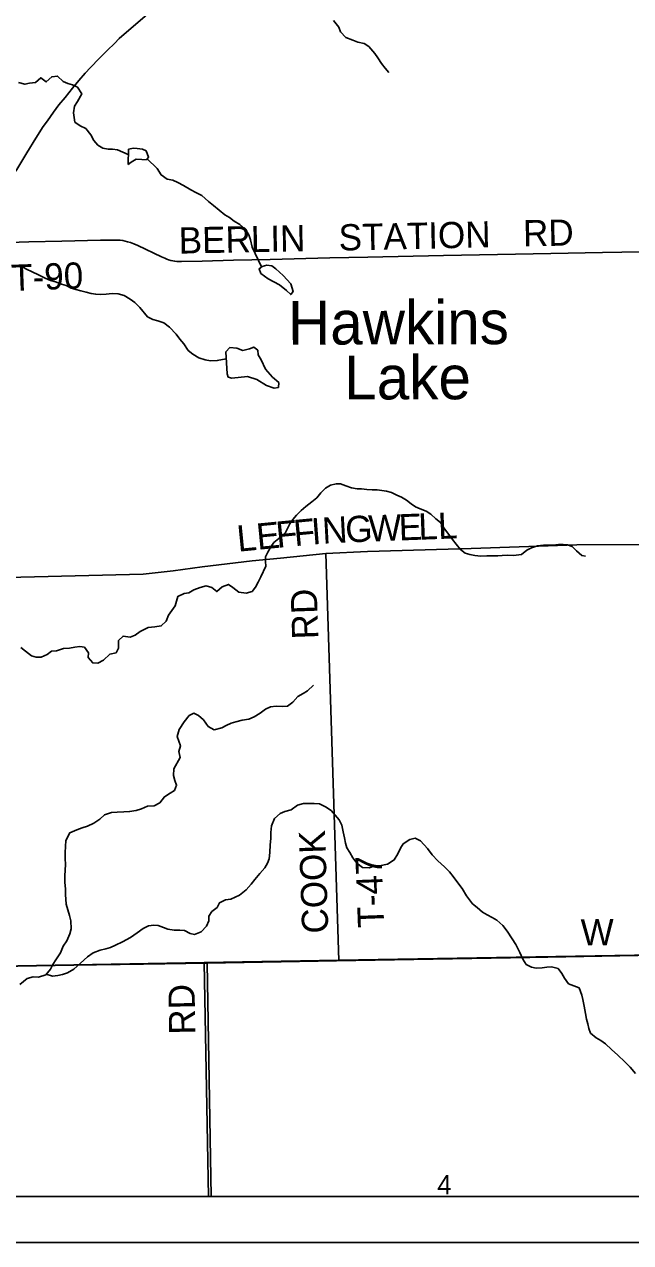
# Model space of a CAD drawing. Extents: x 0 to 34, y 0 to 22.
# Drawn here: x 5.185 to 6.498, y 13.024 to 15.664 of the extents above; entities that cross this region are included whole.
import ezdxf

# ---------------------------------------------------------------- set-up
doc = ezdxf.new("R2010")
doc.units = 0
for name, color, linetype in [('GM_X_Corporation', 7, 'Continuous'), ('GM_X_County_Road', 7, 'Continuous'), ('GM_X_County_Road_Text', 7, 'Continuous'), ('GM_X_Minor_Lake', 7, 'Continuous'), ('GM_X_Minor_River', 7, 'Continuous'), ('GM_X_Minor_River_Text', 7, 'Continuous'), ('GM_X_Rail_Line', 7, 'Continuous'), ('GM_X_Section_Text', 7, 'Continuous'), ('GM_X_Township_Road', 7, 'Continuous'), ('GM_X_Township_Road_Text', 7, 'Continuous'), ('SH_Data', 7, 'Continuous')]:
    doc.layers.add(name, color=color, linetype=linetype)

msp = doc.modelspace()

# ---------------------------------------------------------------- linework, layer by layer
at = {"layer": 'GM_X_Corporation'}
msp.add_lwpolyline([(7.0169, 18.7868), (5.8701, 18.7643), (5.4919, 18.7569), (4.784, 18.7437), (3.4438, 18.7173), (3.4438, 13.5923), (3.5133, 13.5939), (4.9278, 13.619), (5.5741, 13.6306), (5.8662, 13.6357), (7.1049, 13.6572)], dxfattribs=at)
for points in [[(3.5203, 13.1239), (9.7254, 13.1239), (9.7218, 13.5975), (9.7208, 13.7198), (9.6344, 13.7177), (8.628, 13.6922), (8.1719, 13.6806), (7.1291, 13.6578), (7.1049, 13.6572), (5.8662, 13.6357), (5.5741, 13.6306), (4.9278, 13.619), (3.5133, 13.5939)], [(4.5581, 13.1239), (5.5897, 13.1239), (5.5806, 13.6297), (5.4429, 13.6273), (5.0357, 13.6214), (4.6031, 13.6154), (4.55, 13.6145)], [(5.5897, 13.1239), (6.6031, 13.1239), (6.5922, 13.6472), (6.2801, 13.6415), (5.861, 13.6345), (5.5806, 13.6297)]]:
    msp.add_lwpolyline(points, close=True, dxfattribs=at)
at = {"layer": 'GM_X_County_Road'}
msp.add_lwpolyline([(3.5135, 13.5934), (4.928, 13.6184), (5.5743, 13.6301), (5.8664, 13.6351), (7.1051, 13.6567)], dxfattribs=at)
at = {"layer": 'GM_X_Minor_Lake'}
for points in [[(5.4097, 15.3599), (5.416, 15.3654), (5.4269, 15.3714), (5.4391, 15.3713), (5.449, 15.3704), (5.4538, 15.3762), (5.4485, 15.3897), (5.4408, 15.3937), (5.429, 15.3946), (5.421, 15.3952), (5.41, 15.3934)], [(5.41, 15.3934), (5.4097, 15.3599)], [(5.6997, 15.1394), (5.6934, 15.1343), (5.6967, 15.1242), (5.7129, 15.1124), (5.7372, 15.0993), (5.7523, 15.0871), (5.7617, 15.0782), (5.7668, 15.0851), (5.7619, 15.1014), (5.7455, 15.1196), (5.7295, 15.1337), (5.7206, 15.1407), (5.71, 15.142)], [(5.71, 15.142), (5.6997, 15.1394)], [(5.6238, 14.9065), (5.6266, 14.8993), (5.6339, 14.8969), (5.6684, 14.9007), (5.6883, 14.8943), (5.7096, 14.8815), (5.7261, 14.8758), (5.7352, 14.8772), (5.7361, 14.8875), (5.7221, 14.8993), (5.7072, 14.9168), (5.6976, 14.9368), (5.6913, 14.9476), (5.6903, 14.9575), (5.6818, 14.9645), (5.6727, 14.9605), (5.658, 14.9571), (5.6449, 14.9621), (5.6297, 14.9633), (5.6211, 14.954)], [(5.6211, 14.954), (5.6238, 14.9065)]]:
    msp.add_lwpolyline(points, dxfattribs=at)
at = {"layer": 'GM_X_Minor_River'}
for points in [[(5.8547, 15.6719), (5.8657, 15.6577), (5.8697, 15.6479), (5.881, 15.6353), (5.8964, 15.6296), (5.9075, 15.6253), (5.9213, 15.6222), (5.931, 15.6155), (5.9438, 15.601), (5.9505, 15.5913), (5.9588, 15.5793), (5.9663, 15.5692), (5.9745, 15.5592)], [(5.172, 15.5376), (5.1857, 15.5341), (5.1956, 15.5362), (5.2089, 15.5377), (5.22, 15.5482), (5.232, 15.539), (5.2439, 15.5503), (5.2565, 15.5517), (5.2689, 15.5399), (5.2785, 15.5359), (5.2889, 15.5327), (5.2996, 15.5276), (5.3091, 15.513), (5.3, 15.4969), (5.2934, 15.4864), (5.291, 15.4723), (5.2924, 15.4621), (5.2942, 15.4519), (5.3058, 15.4438)], [(5.3058, 15.4438), (5.3177, 15.438), (5.3283, 15.4242), (5.335, 15.4118), (5.344, 15.4017), (5.3548, 15.3955), (5.3659, 15.3935), (5.3754, 15.3933), (5.3861, 15.3921), (5.4099, 15.3815)], [(5.4505, 15.3721), (5.4723, 15.3511), (5.4809, 15.3377), (5.4937, 15.3285), (5.5063, 15.3261), (5.5171, 15.3214), (5.5294, 15.3149), (5.5452, 15.3053), (5.5564, 15.2991), (5.5691, 15.2926), (5.5835, 15.28), (5.5943, 15.2715), (5.6068, 15.2608), (5.6192, 15.2512), (5.6288, 15.245), (5.6396, 15.2376), (5.6512, 15.2299), (5.6636, 15.2196), (5.6711, 15.208), (5.6744, 15.197), (5.6782, 15.1807), (5.6988, 15.1387)], [(5.1747, 15.1411), (5.189, 15.1331), (5.2017, 15.1273), (5.2155, 15.1208), (5.2294, 15.1135), (5.2413, 15.1088), (5.2524, 15.1057), (5.2651, 15.101), (5.2754, 15.0978), (5.2858, 15.0924), (5.2961, 15.0896), (5.3069, 15.0864), (5.3187, 15.0833), (5.3291, 15.0809), (5.3394, 15.0788), (5.3504, 15.0787), (5.3622, 15.0794), (5.3747, 15.0804), (5.3877, 15.0796), (5.4011, 15.0765), (5.4142, 15.0681), (5.4243, 15.0611), (5.4348, 15.0503), (5.4512, 15.0302), (5.4628, 15.0243), (5.4735, 15.0212), (5.4865, 15.0169), (5.4993, 15.0077), (5.5133, 14.9928), (5.5216, 14.9813), (5.5302, 14.9712), (5.5393, 14.9573), (5.5497, 14.9488), (5.5629, 14.9412), (5.5767, 14.9366), (5.5881, 14.9345), (5.6026, 14.9353), (5.622, 14.9393)], [(5.6969, 14.4663), (5.7078, 14.4899), (5.7068, 14.4996), (5.7068, 14.5102), (5.712, 14.5198), (5.7184, 14.5313), (5.7251, 14.5408), (5.7399, 14.5523), (5.7497, 14.5612), (5.7545, 14.5711), (5.7601, 14.5814), (5.7665, 14.591), (5.774, 14.6005), (5.7842, 14.6101), (5.7948, 14.6189), (5.8073, 14.6289), (5.8182, 14.6381), (5.8272, 14.6489), (5.837, 14.6588), (5.848, 14.665), (5.8602, 14.6681), (5.8697, 14.6678), (5.8815, 14.6641), (5.8937, 14.6593), (5.9059, 14.6571), (5.9154, 14.6576), (5.9265, 14.6558), (5.9386, 14.6551), (5.9493, 14.6552), (5.9691, 14.6523), (5.9805, 14.6494), (5.9916, 14.6434), (6.0015, 14.6389), (6.013, 14.6325), (6.0226, 14.6246), (6.0325, 14.6186), (6.0425, 14.6141), (6.0554, 14.6086), (6.0654, 14.6022), (6.0761, 14.592), (6.0861, 14.5845), (6.0953, 14.5709), (6.1042, 14.5584), (6.1127, 14.5474), (6.12, 14.5376), (6.1296, 14.5255), (6.1399, 14.518), (6.1502, 14.5151), (6.1609, 14.5129), (6.1738, 14.5111), (6.1864, 14.5119), (6.1978, 14.5124), (6.2107, 14.5121), (6.2202, 14.513), (6.232, 14.5138), (6.2442, 14.5132), (6.2617, 14.5148), (6.2737, 14.5244), (6.2836, 14.5298), (6.2965, 14.5341), (6.3094, 14.535), (6.3307, 14.5352), (6.3421, 14.5364), (6.3524, 14.5369), (6.3619, 14.5358), (6.3714, 14.5321), (6.3814, 14.5226), (6.3925, 14.5129), (6.4005, 14.5114)], [(5.1868, 14.3057), (5.2003, 14.2957), (5.2102, 14.2924), (5.2208, 14.2926), (5.2339, 14.2986), (5.2436, 14.3056), (5.2542, 14.3066), (5.2693, 14.311), (5.2826, 14.3121), (5.2943, 14.3142), (5.3045, 14.3155), (5.3147, 14.3142), (5.3237, 14.3018), (5.3231, 14.2919), (5.3328, 14.28), (5.3438, 14.2794), (5.3558, 14.2861), (5.37, 14.2989), (5.3835, 14.3018), (5.3887, 14.3118), (5.3884, 14.3285), (5.3984, 14.3382), (5.4136, 14.3359), (5.4249, 14.3399), (5.4357, 14.3481), (5.453, 14.3571), (5.467, 14.3585), (5.4814, 14.3603), (5.4922, 14.3708), (5.4972, 14.3834), (5.5042, 14.3934), (5.5116, 14.4038), (5.5141, 14.4142), (5.5169, 14.4237), (5.5308, 14.4304), (5.541, 14.4321), (5.5519, 14.4381), (5.5655, 14.4436), (5.5787, 14.4473), (5.5909, 14.4434), (5.6016, 14.4348), (5.6136, 14.4453), (5.6267, 14.4501), (5.6363, 14.4435), (5.649, 14.4335), (5.665, 14.4311), (5.6782, 14.4348), (5.6856, 14.4444), (5.6911, 14.4552), (5.6969, 14.4663)], [(5.1772, 14.3134), (5.1868, 14.3057)], [(5.3099, 13.9225), (5.3212, 13.9261), (5.3354, 13.9328), (5.3485, 13.9415), (5.3586, 13.9508), (5.3733, 13.956), (5.3854, 13.957), (5.3998, 13.9573), (5.4126, 13.9579), (5.427, 13.9604), (5.4387, 13.9641), (5.4518, 13.9697), (5.4662, 13.9703), (5.4779, 13.9766), (5.4882, 13.9901), (5.5002, 13.9976), (5.5099, 14.0038), (5.5143, 14.0149), (5.5107, 14.0255), (5.5078, 14.0361), (5.5087, 14.0509), (5.5219, 14.0751), (5.5194, 14.0883), (5.5229, 14.1002), (5.5193, 14.1104), (5.5154, 14.1205), (5.5204, 14.1358), (5.5307, 14.1524), (5.5418, 14.1659), (5.5519, 14.171), (5.5619, 14.1659), (5.5727, 14.157), (5.5828, 14.1424), (5.5958, 14.135), (5.6124, 14.1391), (5.6222, 14.1446), (5.6331, 14.1494), (5.6428, 14.1526), (5.6564, 14.1559), (5.6712, 14.1585), (5.6824, 14.1633), (5.6955, 14.1715), (5.7068, 14.1801), (5.7177, 14.1848), (5.7305, 14.1862), (5.743, 14.1857), (5.7551, 14.1863), (5.7667, 14.1953), (5.7771, 14.2076), (5.7887, 14.2136), (5.7985, 14.2198), (5.8115, 14.2322)], [(5.2319, 13.6054), (5.2457, 13.601), (5.2574, 13.6028), (5.2676, 13.6049), (5.2778, 13.6085), (5.292, 13.6164), (5.3066, 13.6295), (5.3211, 13.6435), (5.3334, 13.6517), (5.3489, 13.6577), (5.3609, 13.6606), (5.3715, 13.6635), (5.3824, 13.6682), (5.397, 13.6757), (5.4143, 13.6852), (5.4293, 13.6953), (5.442, 13.7047), (5.4536, 13.7106), (5.4653, 13.712), (5.4748, 13.711), (5.4859, 13.7067), (5.4958, 13.7031), (5.5095, 13.7011), (5.5216, 13.7009), (5.5319, 13.7), (5.5437, 13.6938), (5.5536, 13.6913), (5.5675, 13.6973), (5.579, 13.7096), (5.5841, 13.7215), (5.5847, 13.7314), (5.591, 13.7414), (5.6022, 13.7503), (5.6073, 13.7603), (5.6204, 13.767), (5.6321, 13.7684), (5.6506, 13.7767), (5.6651, 13.788), (5.6763, 13.8004), (5.6837, 13.8108), (5.6948, 13.8239), (5.7059, 13.8363), (5.7114, 13.8459), (5.715, 13.8558), (5.7163, 13.8695), (5.7171, 13.8859), (5.7188, 13.8996), (5.7189, 13.9129), (5.7202, 13.927), (5.7267, 13.9431), (5.7386, 13.9535), (5.7488, 13.9579), (5.7631, 13.962), (5.7765, 13.9721), (5.7894, 13.9754), (5.8026, 13.9753), (5.8125, 13.9755), (5.8242, 13.9746), (5.8372, 13.968), (5.8491, 13.9606), (5.8584, 13.9498), (5.8666, 13.94), (5.8724, 13.9288), (5.8757, 13.9144), (5.8783, 13.9008), (5.8808, 13.8894), (5.8836, 13.8792), (5.8902, 13.8695), (5.8965, 13.8578), (5.9047, 13.8462), (5.9173, 13.8369), (5.9318, 13.8357), (5.9438, 13.8401), (5.9544, 13.8407), (5.9718, 13.8437), (5.986, 13.8531), (5.9937, 13.8665), (5.9996, 13.8784), (6.0054, 13.888), (6.0197, 13.8974), (6.0317, 13.9003), (6.0432, 13.8948), (6.0579, 13.8776), (6.068, 13.8645), (6.0804, 13.8514), (6.0947, 13.838), (6.1058, 13.8272), (6.1136, 13.8171), (6.1221, 13.8063), (6.133, 13.7909), (6.1428, 13.7751), (6.156, 13.7583), (6.166, 13.7501), (6.1776, 13.7401), (6.1875, 13.7342), (6.1982, 13.7283), (6.2086, 13.7225), (6.2213, 13.7113), (6.231, 13.699), (6.2415, 13.6824), (6.2497, 13.6697)], [(5.1748, 13.5833), (5.1905, 13.5962), (5.2037, 13.5998), (5.215, 13.5989), (5.2309, 13.6042), (5.2409, 13.6161), (5.2464, 13.6265), (5.2526, 13.6369), (5.263, 13.6515), (5.2684, 13.666), (5.2769, 13.678), (5.2834, 13.6929), (5.2862, 13.704), (5.2855, 13.7211), (5.2827, 13.7324), (5.279, 13.7449), (5.2754, 13.757), (5.2744, 13.768), (5.2739, 13.7774), (5.2736, 13.7907), (5.2723, 13.8044), (5.2724, 13.8192), (5.2733, 13.8306), (5.2738, 13.8439), (5.2732, 13.8557), (5.2733, 13.869), (5.2735, 13.8826), (5.2744, 13.8952), (5.2828, 13.9121), (5.2986, 13.9185), (5.3099, 13.9225)], [(6.2497, 13.6697), (6.2584, 13.6524), (6.2651, 13.6381), (6.2721, 13.6268), (6.2836, 13.6209), (6.2939, 13.6185), (6.3063, 13.6191), (6.3165, 13.6208), (6.3268, 13.6218), (6.3412, 13.6179), (6.349, 13.6074), (6.3549, 13.5972), (6.3638, 13.5849), (6.3753, 13.5801), (6.3867, 13.5758), (6.3923, 13.5603), (6.3948, 13.5505), (6.3977, 13.5361), (6.4006, 13.5202), (6.4027, 13.5081), (6.4056, 13.4983), (6.408, 13.4881), (6.4116, 13.4779), (6.4236, 13.4675), (6.4339, 13.4616), (6.4439, 13.4546), (6.4566, 13.4427), (6.4705, 13.4304), (6.4859, 13.4159), (6.4971, 13.4039), (6.5087, 13.3901)]]:
    msp.add_lwpolyline(points, dxfattribs=at)
at = {"layer": 'GM_X_Rail_Line'}
msp.add_lwpolyline([(5.1658, 15.3457), (5.19, 15.3853), (5.2095, 15.4175), (5.2254, 15.4423), (5.2345, 15.455), (5.2477, 15.4735), (5.2594, 15.4891), (5.2727, 15.5054), (5.2886, 15.5253), (5.303, 15.5422), (5.3163, 15.5578), (5.3282, 15.5705), (5.3469, 15.5897), (5.3648, 15.608), (5.3797, 15.6226), (5.3904, 15.6328), (5.4967, 15.7256)], dxfattribs=at)
at = {"layer": 'GM_X_Township_Road'}
for p, q in [((5.8664, 13.6351), (5.8379, 14.517)), ((5.5838, 13.1239), (5.5743, 13.6301))]:
    msp.add_line(p, q, dxfattribs=at)
for points in [[(5.1306, 15.1906), (5.1942, 15.1923), (5.2656, 15.1942), (5.3496, 15.1961), (5.3786, 15.1965), (5.3869, 15.1963), (5.3925, 15.1959), (5.3977, 15.1953), (5.4027, 15.1943), (5.4084, 15.1928), (5.4147, 15.1909), (5.4216, 15.1881), (5.4302, 15.1844), (5.482, 15.1601), (5.4887, 15.1569), (5.4931, 15.1551), (5.4973, 15.1536), (5.502, 15.1523), (5.5064, 15.1512), (5.5106, 15.1504), (5.5147, 15.15), (5.5194, 15.1498), (5.5253, 15.1497), (5.5702, 15.1508), (5.6375, 15.1527), (5.7172, 15.1546), (5.8462, 15.1577), (5.9291, 15.1594), (6.093, 15.1628), (6.2492, 15.166), (6.3255, 15.1672), (6.4372, 15.1693), (6.6899, 15.1737)], [(7.1047, 14.5497), (6.8428, 14.5444), (6.5863, 14.5369), (6.3815, 14.5363), (6.1527, 14.5277), (5.9285, 14.5217), (5.8379, 14.517), (5.7397, 14.507), (5.678, 14.5012), (5.5699, 14.4885), (5.5067, 14.4797), (5.442, 14.4727), (4.9111, 14.4597)]]:
    msp.add_lwpolyline(points, dxfattribs=at)
at = {"layer": 'SH_Data'}
for p, q in [((3.4438, 13.1239), (10.2438, 13.1239)), ((3.3438, 13.0239), (10.3438, 13.0239))]:
    msp.add_line(p, q, dxfattribs=at)

# ---------------------------------------------------------------- texts
at = {"layer": 'GM_X_County_Road_Text'}
msp.add_text('W', height=0.0568, rotation=0.7248, dxfattribs=at).set_placement((6.3906, 13.6677))
at = {"layer": 'GM_X_Minor_River_Text'}
for s, rotation, p in [('Hawkins', 0.1287, (5.756, 14.9698)), ('Lake', 0.1288, (5.8777, 14.8509))]:
    msp.add_text(s, height=0.09474, rotation=rotation, dxfattribs=at).set_placement(p)
at = {"layer": 'GM_X_Section_Text'}
msp.add_text('4', height=0.0419, rotation=0, dxfattribs=at).set_placement((6.0792, 13.1282))
at = {"layer": 'GM_X_Township_Road_Text'}
for s, height, rotation, p in [('STATION', 0.05682, 1.2539, (5.8662, 15.1735)), ('RD', 0.05682, 0.9784, (6.2656, 15.1827)), ('BERLIN', 0.05682, 1.1421, (5.5196, 15.1669)), ('T-90', 0.05682, 2.1212, (5.157, 15.086)), ('G', 0.0568, 2.1533, (5.8811, 14.541)), ('W', 0.0568, 2.1364, (5.9311, 14.5429)), ('E', 0.0568, 2.1392, (5.9968, 14.5453)), ('L', 0.0568, 2.1347, (6.0393, 14.5469)), ('L', 0.0568, 2.1392, (6.0818, 14.5485)), ('L', 0.0568, 5.5844, (5.6479, 14.5209)), ('E', 0.0568, 5.586, (5.6902, 14.5251)), ('F', 0.0568, 5.5825, (5.7325, 14.5292)), ('F', 0.0568, 5.3768, (5.7706, 14.5329)), ('I', 0.0568, 4.4071, (5.8085, 14.5365)), ('N', 0.0568, 3.1198, (5.8314, 14.5383)), ('RD', 0.05682, 91.9758, (5.8219, 14.3321)), ('COOK', 0.05682, 91.9414, (5.8435, 13.6946)), ('T-47', 0.05682, 92.1213, (5.9644, 13.7073)), ('RD', 0.05682, 90.9872, (5.5552, 13.475))]:
    msp.add_text(s, height=height, rotation=rotation, dxfattribs=at).set_placement(p)

doc.saveas('drawing.dxf')
